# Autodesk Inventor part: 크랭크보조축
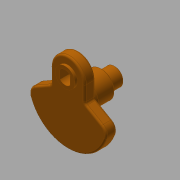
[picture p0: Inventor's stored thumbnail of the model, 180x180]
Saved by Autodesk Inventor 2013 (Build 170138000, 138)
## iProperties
Created: 2016-11
Part Number: 크랭크보조축
Material: 강철, 탄소
Document SubType Name: Modeling
Designer: mduedu
Density: 7.87 g/cm^3
Mass: 629.251 g
Surface Area: 163.688 cm^2
Volume: 79.9557 cm^3
Author: mduedu
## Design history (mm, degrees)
sketch "스케치1" dims "d8" = 65
  geometry: L1 (-19, 26.368)-(-19, 8.368); L2 (-19, 8.368)-(-44.545, -6.381); L3 (0, 26.368)-(0, -45); L4 (19, 26.368)-(19, 8.368); L5 (19, 8.368)-(44.545, -6.381); C1 r 10 at (0, 0); C2 r 17.5 at (0, 0); A1 r 45 centre (0, 0) between (-44.545, -6.381) and (0, -45); A2 r 19 centre (0, 26.368) between (0, 45.368) and (-19, 26.368); A3 r 19 centre (0, 26.368) between (19, 26.368) and (0, 45.368); A4 r 45 centre (0, 0) between (0, -45) and (44.545, -6.381); 2 further points
  constraints: 10 end point, 8 point on circle, 6 centre point, 4 coincident, 3 symmetric about line, 2 point on line, 1 parallel, 1 tangent, 1 vertical, 1 vertical alignment, 5 other
  dimensions: "d1" = 20 diameter of C1; "d2" = 35 diameter of C2; "d4" = 18 distance of L1.start L1.end; "d5" = 120 deg angle of L2 L1; "d6" = 45 radius of A1; "d9" = 19 radius of A2
extrude "돌출1" new body sketch "스케치1" distance "d10" = 12; taper "d11" = 0 deg
sketch "스케치2"
  geometry: C1 r 7.5 at (0, 26.368); C2 r 11 at (0, 26.368); A1 r 19 centre (0, 26.368) between (19, 26.368) and (-19, 26.368) reference; 1 further point
  constraints: 2 centre point, 2 coincident
  dimensions: "d16" = 15 diameter of C1; "d17" = 22 diameter of C2
extrude "돌출10" join sketch "스케치1" distance "d46" = 5; taper "d47" = 0 deg
extrude "돌출11" join sketch "스케치1" distance "d48" = 41; taper "d49" = 0 deg
extrude "돌출12" join sketch "스케치2" distance "d50" = 3; taper "d51" = 0 deg
extrude "돌출13" cut sketch "스케치2" stored distance "d52" = 3; taper "d53" = 0 deg
sketch "스케치7"
  geometry: L1 (5.75, -4.815)-(-5.75, -4.815); L2 (-5.75, -4.815)-(-5.75, 4.815); L3 (-5.75, 4.815)-(5.75, 4.815); L4 (5.75, 4.815)-(5.75, -4.815); L5 (5.75, -4.815)-(-5.75, 4.815); L6 (-5.75, -4.815)-(5.75, 4.815); A1 r 7.5 centre (0, 0) between (-5.75, 4.815) and (-5.75, -4.815); A2 r 7.5 centre (0, 0) between (5.75, -4.815) and (5.75, 4.815); 2 further points
  constraints: 12 end point, 4 point on circle, 2 centre point, 2 midpoint, 2 parallel, 1 coincident, 1 horizontal, 1 perpendicular, 2 other
  dimensions: "d54" = 11.5 distance of L2.end L3.end
extrude "돌출14" join sketch "스케치7" stored distance "d56" = 40.75; taper "d57" = 0 deg
sketch "스케치8"
  geometry: C1 r 17.5 at (0, 0) reference; C2 r 15 at (0, 0); 1 further point
  constraints: 1 centre point, 1 coincident
  dimensions: "d58" = 30 diameter of C2
extrude "돌출15" join sketch "스케치8" distance "d59" = 21; taper "d60" = 0 deg
chamfer "모따기3" distance "d61" = 1; stored, may be unused: second distance "d62" = 2, angle "d63" = 45 deg
fillet "모깎기3" dims "d64" = 3, "d65" = 10
fillet "모깎기4" dims "d66" = 2
node "솔리드1"
other parameters: "d3" = 38
